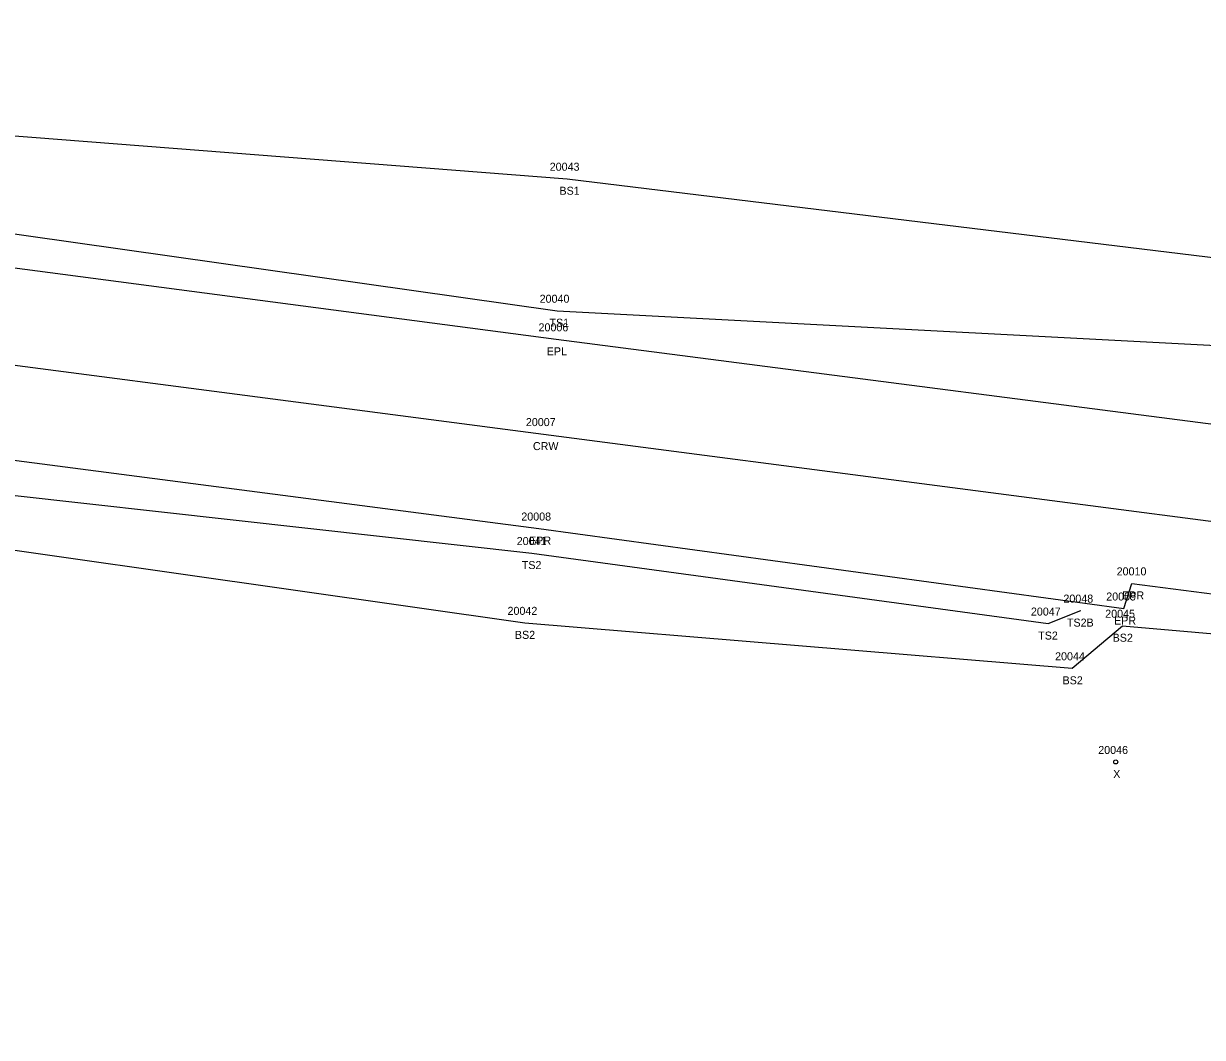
# Model space of a CAD drawing. Extents: x 2080935 to 2082049, y 730754 to 730962.
# Drawn here: x 2081082.6 to 2081229.8, y 730833.2 to 730959.9 of the extents above; entities that cross this region are included whole.
import ezdxf

# ---------------------------------------------------------------- set-up
doc = ezdxf.new("R2010")
doc.units = 0
for name, color, linetype in [('RD_DTM_BkLn1', 7, 'Continuous'), ('RD_DTM_BkLn2', 7, 'Continuous'), ('RD_EX_Road', 7, 'Continuous'), ('RD_EX_Road_txCode', 7, 'Continuous'), ('RD_Sketch8', 7, 'Continuous'), ('RD_SMD_Locator', 7, 'Continuous'), ('RD_SMD_Misc', 7, 'Continuous')]:
    doc.layers.add(name, color=color, linetype=linetype)

msp = doc.modelspace()

# ---------------------------------------------------------------- linework, layer by layer
at = {"layer": 'RD_DTM_BkLn1'}
msp.add_lwpolyline([(2080941.25, 730935.08), (2081045.42, 730921.9), (2081147.52, 730908.57), (2081249.67, 730895.22), (2081352.74, 730881.46), (2081412.15, 730874.37), (2081469.7, 730866.51)], dxfattribs=at)
at = {"layer": 'RD_DTM_BkLn2'}
for points in [[(2080945.43, 730959.86), (2081048.27, 730948.4), (2081150.46, 730940.47), (2081258.15, 730927.34), (2081357.17, 730920.11)], [(2080943.5, 730950.5), (2081046.79, 730938.49), (2081149.23, 730923.98), (2081252.89, 730918.53), (2081354.86, 730896.89)], [(2080939.97, 730920.81), (2081043.8, 730905.11), (2081146.06, 730893.71), (2081210.56, 730884.9), (2081214.62, 730886.52)], [(2080937.44, 730917.14), (2081043.42, 730899.5), (2081145.18, 730884.99), (2081213.57, 730879.31), (2081219.84, 730884.63), (2081248.03, 730882.14), (2081293.17, 730875.78), (2081295.97, 730870.07), (2081341.8, 730864.37), (2081343.7, 730868.33), (2081350.17, 730868.41), (2081364.36, 730860.34), (2081384.26, 730854.27), (2081383.97, 730833.2)]]:
    msp.add_lwpolyline(points, dxfattribs=at)
at = {"layer": 'RD_EX_Road'}
for points in [[(2080942.12, 730947.38), (2081047.3, 730933.82), (2081149.12, 730920.41), (2081250.8, 730907.26), (2081354.36, 730894.35), (2081413.29, 730885.99), (2081474.17, 730877.58), (2081469.7, 730866.51)], [(2080939.88, 730923.83), (2081043.62, 730910.24), (2081146.95, 730896.77), (2081220.01, 730886.78), (2081221.02, 730889.92), (2081249.39, 730886.24), (2081293.86, 730880.24), (2081293.66, 730877.5), (2081351.01, 730869.76), (2081411.83, 730862.33), (2081465.27, 730855.52), (2081469.7, 730866.51)]]:
    msp.add_lwpolyline(points, dxfattribs=at)
at = {"layer": 'RD_SMD_Locator'}
for centre, radius in [((2081150.46, 730940.47), 0.001), ((2081149.23, 730923.98), 0.001), ((2081149.12, 730920.41), 0.001), ((2081147.52, 730908.57), 0.001), ((2081146.95, 730896.77), 0.001), ((2081146.06, 730893.71), 0.001), ((2081221.02, 730889.92), 0.001), ((2081214.62, 730886.52), 0.001), ((2081220.01, 730886.78), 0.001), ((2081145.18, 730884.99), 0.001), ((2081210.56, 730884.9), 0.001), ((2081219.84, 730884.63), 0.001), ((2081213.57, 730879.31), 0.001), ((2081218.99, 730867.61), 0.25)]:
    msp.add_circle(centre, radius, dxfattribs=at)

# ---------------------------------------------------------------- texts
at = {"layer": 'RD_EX_Road_txCode'}
for s, p in [('20006', (2081146.9, 730921.41)), ('EPL', (2081147.92, 730918.41)), ('20008', (2081144.75, 730897.77)), ('EPR', (2081145.72, 730894.77)), ('20010', (2081219.11, 730890.92)), ('20009', (2081217.81, 730887.78)), ('EPR', (2081219.79, 730887.92)), ('EPR', (2081218.78, 730884.78))]:
    msp.add_text(s, height=1, dxfattribs=at).set_placement(p)
at = {"layer": 'RD_Sketch8'}
for s, p in [('20046', (2081216.81, 730868.61)), ('X', (2081218.68, 730865.61))]:
    msp.add_text(s, height=1, dxfattribs=at).set_placement(p)
at = {"layer": 'RD_SMD_Misc'}
for s, p in [('20043', (2081148.3, 730941.47)), ('BS1', (2081149.51, 730938.47)), ('20040', (2081147.04, 730924.98)), ('TS1', (2081148.27, 730921.98)), ('20007', (2081145.32, 730909.57)), ('CRW', (2081146.2, 730906.57)), ('20041', (2081144.18, 730894.71)), ('TS2', (2081144.81, 730891.71)), ('20048', (2081212.46, 730887.52)), ('20042', (2081143.03, 730885.99)), ('20047', (2081208.4, 730885.9)), ('20045', (2081217.68, 730885.63)), ('TS2B', (2081212.9, 730884.52)), ('BS2', (2081143.95, 730882.99)), ('TS2', (2081209.31, 730882.9)), ('BS2', (2081218.61, 730882.63)), ('20044', (2081211.42, 730880.31)), ('BS2', (2081212.35, 730877.31))]:
    msp.add_text(s, height=1, dxfattribs=at).set_placement(p)

doc.saveas('drawing.dxf')
